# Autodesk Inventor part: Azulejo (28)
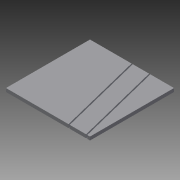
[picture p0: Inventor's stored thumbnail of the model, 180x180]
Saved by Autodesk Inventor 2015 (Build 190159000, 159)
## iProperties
Created: 2015-04
Part Number: Azulejo (28)
Material: Genérico
Document SubType Name: Modeling
Designer: Felipe
Density: 1 g/cm^3
Appearance: Padrão
Author: Felipe
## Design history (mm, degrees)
sketch "Sketch1"
  geometry: L1 (-1510, -7490)-(-1510, -6010); L2 (-3010, -1490)-(-3010, -10); L3 (-2990, 10)-(-1510, 10); L4 (-1510, -10)-(-2990, -10); L5 (-1510, -1490)-(-1510, -10); L6 (-1490, -10)-(-1490, -1490); L7 (-1490, -1490)-(-10, -1490); L8 (-10, -1510)-(-1490, -1510); L9 (-10, -2990)-(-10, -1510); L10 (-10, -5990)-(-10, -4510); L11 (-1490, -7490)-(-10, -7490); L12 (4490, -6010)-(3010, -6010); L13 (10, -1510)-(10, -2990); L14 (10, -3010)-(10, -4490); L15 (10, -4510)-(10, -5990); L16 (10, -5990)-(1490, -5990); L17 (1490, -6010)-(10, -6010); L18 (10, -7490)-(1490, -7490); L19 (1510, -5990)-(2990, -5990); L20 (2990, -6010)-(1510, -6010); L21 (1510, -7490)-(2990, -7490); L22 (4490, 1510)-(4490, 2990); L23 (4490, 10)-(4490, 1490); L24 (4490, -1490)-(4490, -10); L25 (4490, -2990)-(4490, -1510); L26 (3010, -5990)-(4490, -5990); L27 (3010, -7490)-(4490, -7490); L28 (4510, 3010)-(5990, 3010); L29 (5990, 2990)-(4510, 2990); L30 (4510, 2990)-(4510, 1510); L31 (4510, 1510)-(5990, 1510); L32 (5990, 1510)-(5990, 1740.185); L33 (5990, 1760.2)-(5990, 2259.8); L34 (5990, 2279.815)-(5990, 2990); L35 (5990, 1490)-(4510, 1490); L36 (4510, 1490)-(4510, 10); L37 (4510, 10)-(5990, 10); L38 (5990, 10)-(5990, 1490); L39 (5975.983, -10)-(4510, -10); L40 (4510, -10)-(4510, -1490); L41 (5990, -1510)-(5782.897, -1510); L42 (5782.897, -1510)-(5688.66, -1510); L43 (5668.66, -1510)-(5482.895, -1510); L44 (5482.895, -1510)-(5388.656, -1510); L45 (5368.656, -1510)-(4510, -1510); L46 (4510, -1510)-(4510, -2990); L47 (4510, -2990)-(5975.983, -2990); L48 (5990, -2975.728)-(5990, -2837.377); L49 (5990, -2837.377)-(5990, -2536.247); L50 (5990, -2500.476)-(5990, -2317.632); L51 (5990, -2317.632)-(5990, -1510); L52 (5990, -3010)-(4510, -3010); L53 (5990, -4490)-(5990, -3010); L54 (4510, -5990)-(5990, -5990); L55 (5990, -5990)-(5990, -4510); L56 (4510, -7490)-(5990, -7490); L57 (5990, -7490)-(5990, -6310); L58 (5990, -6290)-(5990, -6010); L59 (7490, 4510)-(7490, 5990); L60 (6010, 3010)-(7490, 3010); L61 (7490, 3010)-(7490, 4490); L62 (7490, 2990)-(6010, 2990); L63 (6010, 2990)-(6010, 2279.815); L64 (6010, 2259.8)-(6010, 1760.2)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; A1 r 250 centre (6000, 2010) between (5990, 2259.8) and (5990, 1760.2); A2 r 250 centre (6000, 2010) between (6010, 1760.2) and (6010, 2259.8); A3 r 270 centre (6000, 2010) between (5990, 2279.815) and (5990, 1740.185); A4 r 270 centre (6000, 2010) between (6010, 1740.185) and (6010, 2279.815); A5 r 3010.017 centre (0, 0) between (-1490, -2615.358) and (-346.554, -2990); A6 r 2990.017 centre (0, 0) between (-1490, -2592.316) and (-10, -2990); A7 r 3010.017 centre (0, 0) between (-2603.863, -1510) and (-1510, -2603.863); A8 r 2990.017 centre (0, 0) between (-2580.717, -1510) and (-1510, -2580.717); A9 r 3010.017 centre (0, 0) between (-2990, -346.554) and (-2615.358, -1490); A10 r 2990.017 centre (0, 0) between (-2990, -10) and (-2592.316, -1490); A11 r 2131.367 centre (7500, -1500) between (7490, 631.344) and (6010, 24.017); A12 r 2131.367 centre (7500, -1500) between (5975.983, -10) and (5368.656, -1490); A13 r 2131.367 centre (7500, -1500) between (5368.656, -1510) and (5975.983, -2990); A14 r 2131.367 centre (7500, -1500) between (6010, -3024.017) and (7190, -3608.703); A15 r 1831.367 centre (7500, -1500) between (7490.321, 331.342) and (6463.753, 10); A16 r 1831.367 centre (7500, -1500) between (6435.196, -10) and (6010, -435.196); A17 r 1831.367 centre (7500, -1500) between (5990, -463.753) and (5668.66, -1490); A18 r 1831.367 centre (7500, -1500) between (5668.66, -1510) and (5990, -2536.247); A19 r 1831.367 centre (7500, -1500) between (6010, -2564.804) and (6435.196, -2990); A20 r 1831.367 centre (7500, -1500) between (6463.753, -3010) and (7490, -3331.34); A21 r 2111.367 centre (7500, -1500) between (7490.047, 611.344) and (6024.272, 10); A22 r 2111.367 centre (7500, -1500) between (5990, -24.272) and (5388.656, -1490); A23 r 2111.367 centre (7500, -1500) between (5388.656, -1510) and (5990, -2975.728); A24 r 2111.367 centre (7500, -1500) between (6024.272, -3010) and (7210, -3591.357); A25 r 1811.367 centre (7500, -1500) between (7490.374, 311.342) and (6499.524, 10); A26 r 1811.367 centre (7500, -1500) between (6469.975, -10) and (6010, -469.975); A27 r 1811.367 centre (7500, -1500) between (5990, -499.524) and (5688.66, -1490); A28 r 1811.367 centre (7500, -1500) between (5688.66, -1510) and (5990, -2500.476); A29 r 1811.367 centre (7500, -1500) between (6010, -2530.025) and (6469.975, -2990); A30 r 1811.367 centre (7500, -1500) between (6499.524, -3010) and (7490, -3311.34); A31 r 449.871 centre (7499.449, -4060.672) between (7510, -4510.419) and (7521.546, -4510); 9 further points
  constraints: 698 end point, 64 point on circle, 31 centre point, 11 point on line, 1 other
extrude "Extrusion1" new body sketch "Sketch1" distance "d0" = 60; taper "d1" = 0 deg
extrude "Extrusion2" new body sketch "Sketch1" distance "d2" = 60; taper "d3" = 0 deg
extrude "Extrusion3" new body sketch "Sketch1" distance "d4" = 60; taper "d5" = 0 deg
body "Solid1"
body "Solid2"
body "Solid3"
